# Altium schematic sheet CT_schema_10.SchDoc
size 277 x 170 mm
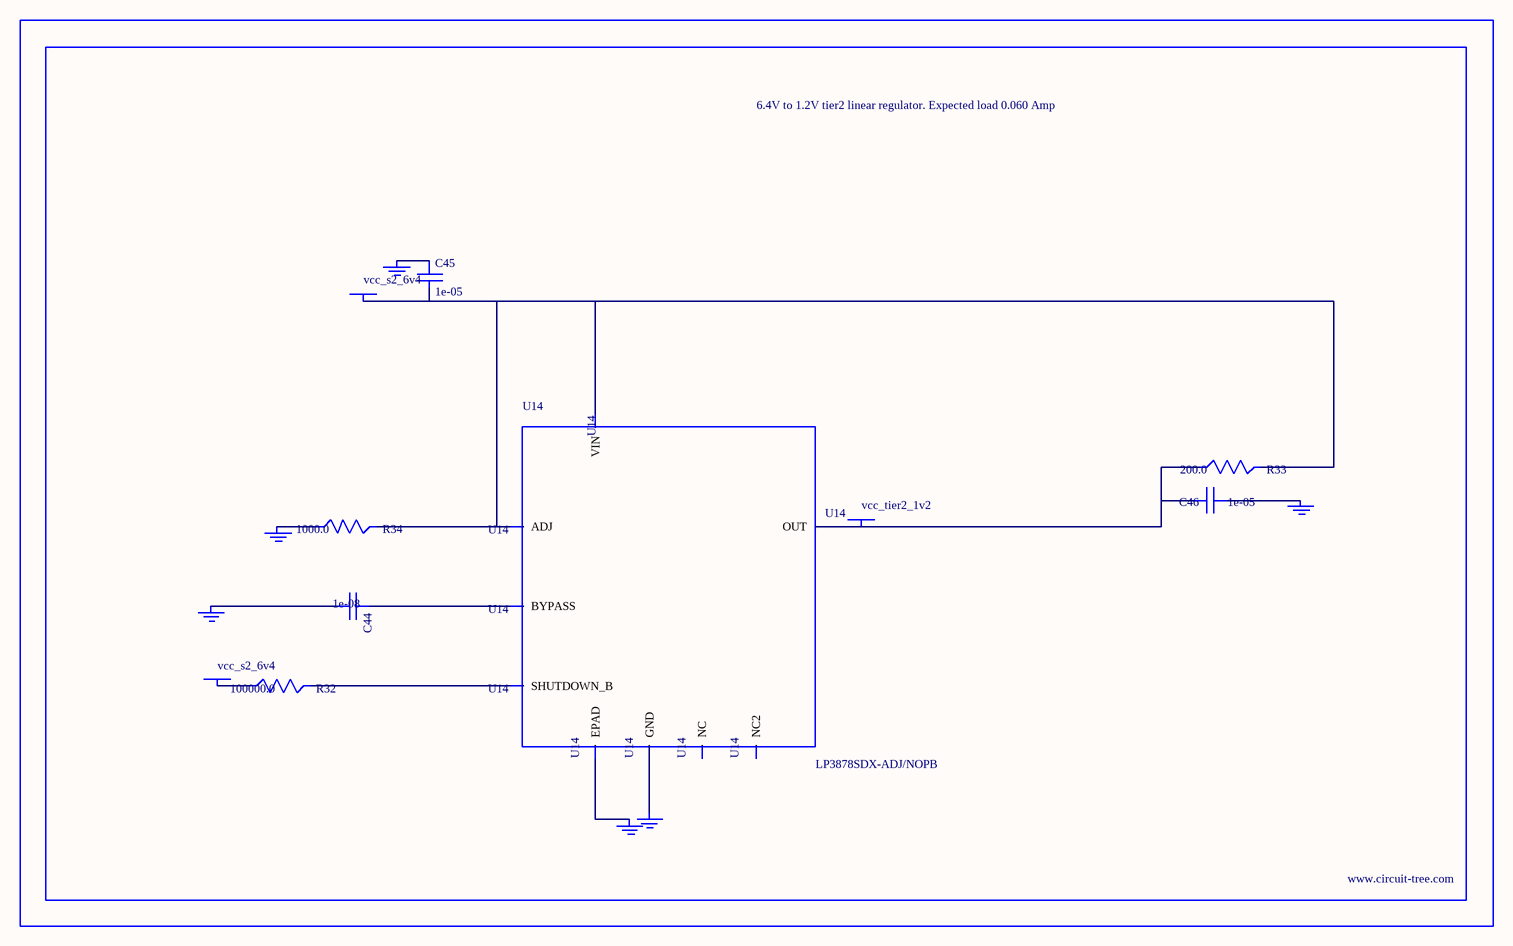
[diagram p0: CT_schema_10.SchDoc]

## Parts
BORDER9  (no value)
C44  1e-08  [C0402]
C45  1e-05  [C1206]
C46  1e-05  [C0805]
GND_INSTANCE_9_0  (no value)
GND_INSTANCE_9_1  (no value)
GND_INSTANCE_9_2  (no value)
GND_INSTANCE_9_3  (no value)
GND_INSTANCE_9_4  (no value)
GND_INSTANCE_9_5  (no value)
POWER_INSTANCE_9_0  vcc_s2_6v4
POWER_INSTANCE_9_1  vcc_s2_6v4
POWER_INSTANCE_9_2  vcc_tier2_1v2
R32  100000.0  [R0603]
R33  200.0  [R0603]
R34  1000.0  [R0603]
U14  LP3878SDX-ADJ/NOPB  [WSON-8]

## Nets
NetC44_1: C44.1 U14.1(BYPASS)
NetC44_2: C44.2 GND_INSTANCE_9_0.0(GND)
NetC45_1: C45.1 GND_INSTANCE_9_1.0(GND)
NetC45_2: C45.2 POWER_INSTANCE_9_0.0(PWR) R33.2 R34.2 U14.4(VIN) U14.6(ADJ)
NetC46_1: C46.1 GND_INSTANCE_9_2.0(GND)
NetC46_2: C46.2 POWER_INSTANCE_9_2.0(PWR) R33.1 U14.5(OUT)
NetGND_INSTANCE_9_3_0: GND_INSTANCE_9_3.0(GND) R34.1
NetGND_INSTANCE_9_4_0: GND_INSTANCE_9_4.0(GND) U14.PAD(EPAD)
NetGND_INSTANCE_9_5_0: GND_INSTANCE_9_5.0(GND) U14.3(GND)
NetPOWER_INSTANCE_9_1_0: POWER_INSTANCE_9_1.0(PWR) R32.1
NetR32_2: R32.2 U14.8(SHUTDOWN_B)

Not connected (* = marked no-connect by the designer): U14 2(NC) 7(NC2)

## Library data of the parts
BORDER9 = BORDER_PAGE9
C44 = C0402C103K3RAC
C45 = C1206C106K3RACTU
C46 = GRM219R60J106ME19D
GND_INSTANCE_9_0-GND_INSTANCE_9_5 = GND
POWER_INSTANCE_9_0-POWER_INSTANCE_9_2 = PWR
R32 = RC0603JR-07100KL
R33 = RC0603JR-07200RL
R34 = RC0603JR-071KL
